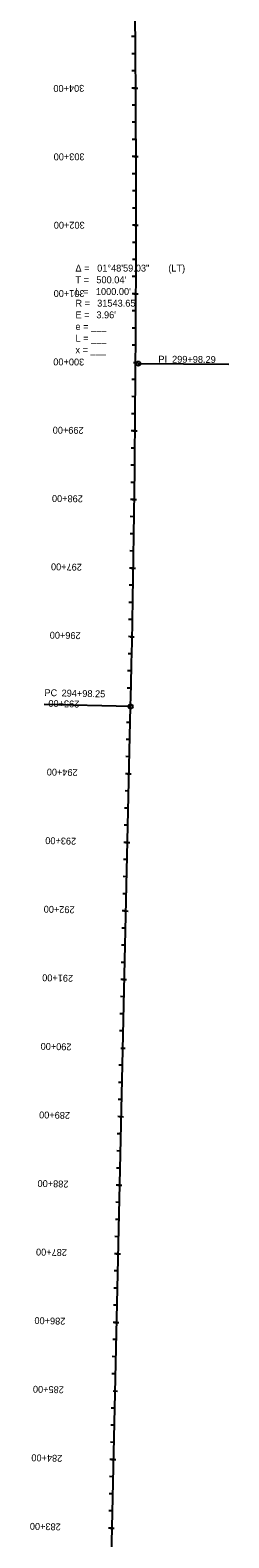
# Model space of a CAD drawing. Extents: x 23417911 to 23421158, y 6737892 to 6791804.
# Drawn here: x 23418105 to 23418395, y 6754767 to 6756965 of the extents above; entities that cross this region are included whole.
import ezdxf

# ---------------------------------------------------------------- set-up
doc = ezdxf.new("R2010")
doc.units = 0
for name, color, linetype in [('Alignment', 7, 'Continuous'), ('TextAlignment', 7, 'Continuous'), ('TextAlignmentLrg', 7, 'Continuous'), ('TextAlignmentSml', 7, 'Continuous')]:
    doc.layers.add(name, color=color, linetype=linetype)

msp = doc.modelspace()

# ---------------------------------------------------------------- linework, layer by layer
at = {"layer": 'Alignment'}
msp.add_line((23418211.4, 6754177.1), (23418252, 6755979.4), dxfattribs=at)
msp.add_line((23418211.4, 6754177.1), (23418252, 6755979.4), dxfattribs=at)
msp.add_arc((23386716.3, 6756689), 31543.7, 358.71097, 0.52737, dxfattribs=at)
msp.add_arc((23386716.3, 6756689), 31543.7, 358.71097, 0.52737, dxfattribs=at)
at = {"layer": 'TextAlignment'}
for p, q in [((23418263.2, 6756479.3), (23418395.2, 6756478.5)), ((23418395.2, 6756478.5), (23418395.2, 6756478.5)), ((23418252, 6755979.4), (23418126, 6755982.3)), ((23418126, 6755982.3), (23418126, 6755982.3))]:
    msp.add_line(p, q, dxfattribs=at)
for centre in [(23418263.2, 6756479.3), (23418252, 6755979.4)]:
    msp.add_circle(centre, 3.12, dxfattribs=at)
at = {"layer": 'TextAlignmentLrg'}
for p, q in [((23418259.4, 6756881.1), (23418253.9, 6756881.1)), ((23418259.8, 6756781.1), (23418254.4, 6756781.1)), ((23418260, 6756681.1), (23418254.5, 6756681.1)), ((23418259.8, 6756581.1), (23418254.3, 6756581.1)), ((23418256.2, 6756481.1), (23418262.3, 6756481.1)), ((23418258.5, 6756381.1), (23418253, 6756381.2)), ((23418257.3, 6756281.1), (23418251.9, 6756281.2)), ((23418255.9, 6756181.1), (23418250.4, 6756181.2)), ((23418254.1, 6756081.2), (23418248.7, 6756081.3)), ((23418249, 6755981.2), (23418255.1, 6755981.1)), ((23418249.8, 6755881.2), (23418244.3, 6755881.3)), ((23418247.5, 6755781.2), (23418242.1, 6755781.3)), ((23418245.3, 6755681.3), (23418239.8, 6755681.4)), ((23418243, 6755581.3), (23418237.6, 6755581.4)), ((23418237.7, 6755481.4), (23418243.8, 6755481.2)), ((23418238.5, 6755381.3), (23418233.1, 6755381.4)), ((23418236.3, 6755281.4), (23418230.8, 6755281.5)), ((23418234, 6755181.4), (23418228.6, 6755181.5)), ((23418231.8, 6755081.4), (23418226.3, 6755081.5)), ((23418226.5, 6754981.5), (23418232.6, 6754981.4)), ((23418227.3, 6754881.5), (23418221.8, 6754881.6)), ((23418225, 6754781.5), (23418219.6, 6754781.6))]:
    msp.add_line(p, q, dxfattribs=at)
at = {"layer": 'TextAlignmentSml'}
for p, q in [((23418258.8, 6756956.1), (23418253.4, 6756956.1)), ((23418259, 6756931.1), (23418253.6, 6756931.1)), ((23418259.2, 6756906.1), (23418253.8, 6756906.1)), ((23418256.3, 6756881.1), (23418262.4, 6756881.1)), ((23418259.5, 6756856.1), (23418254.1, 6756856.1)), ((23418259.6, 6756831.1), (23418254.2, 6756831.1)), ((23418259.8, 6756806.1), (23418254.3, 6756806.1)), ((23418256.8, 6756781.1), (23418262.9, 6756781.1)), ((23418259.9, 6756756.1), (23418254.4, 6756756.1)), ((23418259.9, 6756731.1), (23418254.5, 6756731.1)), ((23418260, 6756706.1), (23418254.5, 6756706.1)), ((23418256.9, 6756681.1), (23418263, 6756681.1)), ((23418260, 6756656.1), (23418254.5, 6756656.1)), ((23418259.9, 6756631.1), (23418254.5, 6756631.1)), ((23418259.9, 6756606.1), (23418254.4, 6756606.1)), ((23418256.7, 6756581.1), (23418262.8, 6756581.1)), ((23418259.7, 6756556.1), (23418254.2, 6756556.1)), ((23418259.6, 6756531.1), (23418254.1, 6756531.1)), ((23418259.4, 6756506.1), (23418254, 6756506.1)), ((23418256.2, 6756481.1), (23418262.3, 6756481.1)), ((23418259.1, 6756456.1), (23418253.6, 6756456.2)), ((23418258.9, 6756431.1), (23418253.5, 6756431.2)), ((23418258.7, 6756406.1), (23418253.2, 6756406.2)), ((23418255.4, 6756381.2), (23418261.5, 6756381.1)), ((23418258.2, 6756356.1), (23418252.8, 6756356.2)), ((23418257.9, 6756331.1), (23418252.5, 6756331.2)), ((23418257.6, 6756306.1), (23418252.2, 6756306.2)), ((23418254.3, 6756281.2), (23418260.4, 6756281.1)), ((23418257, 6756256.1), (23418251.5, 6756256.2)), ((23418256.6, 6756231.1), (23418251.2, 6756231.2)), ((23418256.3, 6756206.1), (23418250.8, 6756206.2)), ((23418252.8, 6756181.2), (23418258.9, 6756181.1)), ((23418255.5, 6756156.1), (23418250, 6756156.2)), ((23418255, 6756131.1), (23418249.6, 6756131.2)), ((23418254.6, 6756106.1), (23418249.1, 6756106.2)), ((23418251.1, 6756081.2), (23418257.2, 6756081.1)), ((23418253.6, 6756056.2), (23418248.2, 6756056.3)), ((23418253.1, 6756031.2), (23418247.6, 6756031.3)), ((23418252.6, 6756006.2), (23418247.1, 6756006.3)), ((23418249, 6755981.2), (23418255.1, 6755981.1)), ((23418251.5, 6755956.2), (23418246, 6755956.3)), ((23418250.9, 6755931.2), (23418245.4, 6755931.3)), ((23418250.3, 6755906.2), (23418244.9, 6755906.3)), ((23418246.7, 6755881.3), (23418252.8, 6755881.1)), ((23418249.2, 6755856.2), (23418243.8, 6755856.3)), ((23418248.7, 6755831.2), (23418243.2, 6755831.3)), ((23418248.1, 6755806.2), (23418242.6, 6755806.3)), ((23418244.5, 6755781.3), (23418250.6, 6755781.2)), ((23418247, 6755756.2), (23418241.5, 6755756.4)), ((23418246.4, 6755731.2), (23418240.9, 6755731.4)), ((23418245.8, 6755706.2), (23418240.4, 6755706.4)), ((23418242.2, 6755681.3), (23418248.3, 6755681.2)), ((23418244.7, 6755656.3), (23418239.3, 6755656.4)), ((23418244.2, 6755631.3), (23418238.7, 6755631.4)), ((23418243.6, 6755606.3), (23418238.1, 6755606.4)), ((23418240, 6755581.3), (23418246.1, 6755581.2)), ((23418242.5, 6755556.3), (23418237, 6755556.4)), ((23418241.9, 6755531.3), (23418236.4, 6755531.4)), ((23418241.3, 6755506.3), (23418235.9, 6755506.4)), ((23418237.7, 6755481.4), (23418243.8, 6755481.2)), ((23418240.2, 6755456.3), (23418234.8, 6755456.4)), ((23418239.7, 6755431.3), (23418234.2, 6755431.4)), ((23418239.1, 6755406.3), (23418233.6, 6755406.4)), ((23418235.5, 6755381.4), (23418241.6, 6755381.3)), ((23418238, 6755356.3), (23418232.5, 6755356.5)), ((23418237.4, 6755331.3), (23418231.9, 6755331.5)), ((23418236.8, 6755306.3), (23418231.4, 6755306.5)), ((23418233.2, 6755281.4), (23418239.3, 6755281.3)), ((23418235.7, 6755256.4), (23418230.3, 6755256.5)), ((23418235.2, 6755231.4), (23418229.7, 6755231.5)), ((23418234.6, 6755206.4), (23418229.1, 6755206.5)), ((23418231, 6755181.4), (23418237.1, 6755181.3)), ((23418233.5, 6755156.4), (23418228, 6755156.5)), ((23418232.9, 6755131.4), (23418227.4, 6755131.5)), ((23418232.3, 6755106.4), (23418226.9, 6755106.5)), ((23418228.7, 6755081.5), (23418234.8, 6755081.3)), ((23418231.2, 6755056.4), (23418225.8, 6755056.5)), ((23418230.7, 6755031.4), (23418225.2, 6755031.5)), ((23418230.1, 6755006.4), (23418224.6, 6755006.5)), ((23418226.5, 6754981.5), (23418232.6, 6754981.4)), ((23418229, 6754956.4), (23418223.5, 6754956.6)), ((23418228.4, 6754931.4), (23418222.9, 6754931.6)), ((23418227.8, 6754906.4), (23418222.4, 6754906.6)), ((23418224.2, 6754881.5), (23418230.3, 6754881.4)), ((23418226.7, 6754856.5), (23418221.3, 6754856.6)), ((23418226.2, 6754831.5), (23418220.7, 6754831.6)), ((23418225.6, 6754806.5), (23418220.1, 6754806.6)), ((23418222, 6754781.5), (23418228.1, 6754781.4))]:
    msp.add_line(p, q, dxfattribs=at)

# ---------------------------------------------------------------- texts
at = {"layer": 'TextAlignment'}
for s, p in [('Δ = ', (23418171.5, 6756613.5)), ('01°48\'59.03"', (23418203.2, 6756613.5)), (' (LT)', (23418303.2, 6756613.5)), ('T = ', (23418171.5, 6756596.5)), ("500.04'", (23418202, 6756596.5)), ('L = ', (23418171.5, 6756579.4)), ("1000.00'", (23418201.3, 6756579.4)), ('R = ', (23418171.5, 6756562.4)), ('E = ', (23418171.5, 6756545.4)), ("3.96'", (23418202, 6756545.4)), ("31543.65'", (23418203.2, 6756562.4)), ('e = ___ ', (23418171.5, 6756528.3)), ('L = ___', (23418171.5, 6756511.3)), ('x = ___', (23418171.5, 6756494.3))]:
    msp.add_text(s, height=10.02, dxfattribs=at).set_placement(p)
for s, rotation, p in [('PI ', 359.6192, (23418292.4, 6756480.8)), ('299+98.29', 359.6192, (23418312.4, 6756480.7)), ('PC', 358.711, (23418126.2, 6755994.7)), ('294+98.25', 358.711, (23418151.2, 6755994.1))]:
    msp.add_text(s, height=10.02, rotation=rotation, dxfattribs=at).set_placement(p)
at = {"layer": 'TextAlignmentLrg'}
for s, rotation, p in [('300+00', 179.6223, (23418184.3, 6756486.6)), ('295+00', 178.7142, (23418177.2, 6755987.9)), ('290+00', 178.711, (23418165.9, 6755488)), ('285+00', 178.711, (23418154.7, 6754988.1))]:
    msp.add_text(s, height=10.02, rotation=rotation, dxfattribs=at).set_placement(p)
at = {"layer": 'TextAlignmentSml'}
for s, rotation, p in [('304+00', 180.3489, (23418184.4, 6756885.7)), ('303+00', 180.1673, (23418184.8, 6756785.9)), ('302+00', 179.9856, (23418185, 6756686.1)), ('301+00', 179.804, (23418184.8, 6756586.4)), ('300+00', 179.6223, (23418184.3, 6756486.6)), ('299+00', 179.4407, (23418183.5, 6756386.9)), ('298+00', 179.2591, (23418182.4, 6756287.1)), ('297+00', 179.0774, (23418181, 6756187.4)), ('296+00', 178.8958, (23418179.2, 6756087.6)), ('295+00', 178.7142, (23418177.2, 6755987.9)), ('294+00', 178.711, (23418174.9, 6755887.9)), ('293+00', 178.711, (23418172.7, 6755787.9)), ('292+00', 178.711, (23418170.4, 6755687.9)), ('291+00', 178.711, (23418168.2, 6755588)), ('290+00', 178.711, (23418165.9, 6755488)), ('289+00', 178.711, (23418163.7, 6755388)), ('288+00', 178.711, (23418161.4, 6755288)), ('287+00', 178.711, (23418159.2, 6755188.1)), ('286+00', 178.711, (23418156.9, 6755088.1)), ('285+00', 178.711, (23418154.7, 6754988.1)), ('284+00', 178.711, (23418152.4, 6754888.1)), ('283+00', 178.711, (23418150.2, 6754788.2))]:
    msp.add_text(s, height=10.02, rotation=rotation, dxfattribs=at).set_placement(p)

doc.saveas('drawing.dxf')
